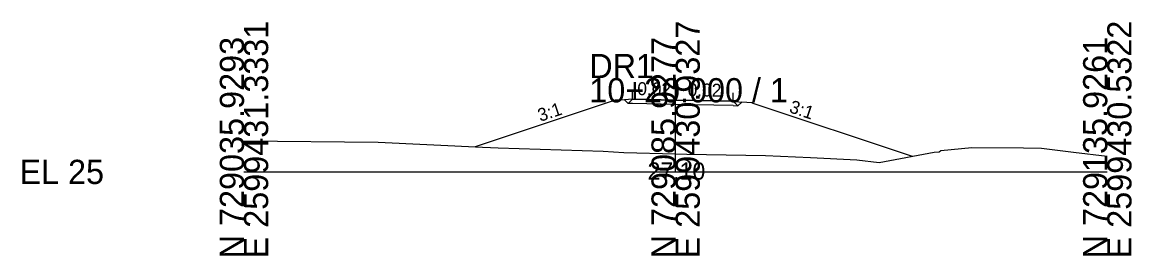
# Model space of a CAD drawing. Extents: x -26 to 1162, y -10 to 9515.
# Drawn here: x -25.7 to 102.8, y 990.3 to 1017.3 of the extents above; entities that cross this region are included whole.
import ezdxf

# ---------------------------------------------------------------- set-up
doc = ezdxf.new("R2010")
doc.units = 0
for name, color, linetype in [('Exist Cross Section Cell', 7, 'Continuous'), ('Exist XS Center Line Elevation Label', 7, 'Continuous'), ('Exist XS Ground Line', 7, 'Continuous'), ('Prop XS Ditch Slope Text', 7, 'Continuous'), ('Prop XS Dump Level', 7, 'Continuous'), ('Prop XS EOT Tick Mark', 7, 'Continuous'), ('Prop XS Finish Grade', 7, 'Continuous'), ('Prop XS Finish Grade Earthwork', 7, 'Continuous'), ('Prop XS Finish Grade Pavement', 7, 'Continuous'), ('Prop XS Pvmt Edge Slope', 7, 'Continuous'), ('Prop XS SE Text', 7, 'Continuous'), ('Prop XS Subgrade Earthwork', 7, 'Continuous')]:
    doc.layers.add(name, color=color, linetype=linetype)

msp = doc.modelspace()

# ---------------------------------------------------------------- linework, layer by layer
at = {"layer": 'Exist Cross Section Cell'}
for p, q in [((50, 1000), (50, 1010.84)), ((0, 1000), (50, 1000)), ((50, 1000), (100, 1000))]:
    msp.add_line(p, q, dxfattribs=at)
at = {"layer": 'Exist XS Ground Line'}
msp.add_lwpolyline([(0, 1003.61), (15.56, 1003.43), (27.61, 1002.87), (28.57, 1002.82), (29.44, 1002.79), (41.59, 1002.4), (44.01, 1002.25), (50, 1002.1), (51.3, 1002.07), (60.42, 1001.91), (65.62, 1001.65), (70.97, 1001.38), (73.59, 1001.09), (79.94, 1002.29), (80.51, 1002.32), (80.71, 1002.47), (84.29, 1002.84), (90.31, 1002.77), (92.36, 1002.74), (96.07, 1002.29), (100, 1001.82)], dxfattribs=at)
at = {"layer": 'Prop XS Dump Level'}
for p, q in [((50, 1008.29), (45, 1008.39)), ((50, 1008.29), (45, 1008.39)), ((56.65, 1008.16), (50, 1008.29)), ((56.65, 1008.16), (50, 1008.29))]:
    msp.add_line(p, q, dxfattribs=at)
at = {"layer": 'Prop XS EOT Tick Mark'}
for p, q in [((45, 1008.39), (45, 1009.39)), ((56.65, 1008.16), (56.65, 1009.16))]:
    msp.add_line(p, q, dxfattribs=at)
at = {"layer": 'Prop XS Finish Grade'}
for p, q in [((45, 1008.39), (44.06, 1008.35)), ((56.65, 1008.16), (57.68, 1008.08))]:
    msp.add_line(p, q, dxfattribs=at)
at = {"layer": 'Prop XS Finish Grade Earthwork'}
for p, q in [((43, 1008.31), (26.79, 1002.91)), ((44.06, 1008.35), (43, 1008.31)), ((58.83, 1008), (57.68, 1008.08)), ((58.83, 1008), (77.41, 1001.82))]:
    msp.add_line(p, q, dxfattribs=at)
at = {"layer": 'Prop XS Finish Grade Pavement'}
for p, q in [((45, 1008.39), (50, 1008.29)), ((50, 1008.29), (56.65, 1008.16))]:
    msp.add_line(p, q, dxfattribs=at)
at = {"layer": 'Prop XS Pvmt Edge Slope'}
for p, q in [((44.06, 1008.35), (44.51, 1007.9)), ((45, 1008.39), (44.51, 1007.9)), ((56.65, 1008.16), (57.21, 1007.65))]:
    msp.add_line(p, q, dxfattribs=at)
at = {"layer": 'Prop XS Subgrade Earthwork'}
for p, q in [((44.51, 1007.9), (44.06, 1008.35)), ((44.51, 1007.9), (44.06, 1008.35)), ((45, 1007.89), (44.51, 1007.9)), ((50, 1007.78), (45, 1007.89)), ((56.65, 1007.66), (50, 1007.78)), ((57.21, 1007.65), (57.68, 1008.08)), ((57.68, 1008.08), (57.21, 1007.65)), ((56.65, 1007.66), (57.21, 1007.65))]:
    msp.add_line(p, q, dxfattribs=at)

# ---------------------------------------------------------------- texts
at = {"layer": 'Exist Cross Section Cell'}
for s, p in [('E 2599431.3331', (2.8, 990)), ('E 2599430.9327', (52.8, 990)), ('E 2599430.5322', (102.8, 990)), ('N 729035.9293', (0, 990)), ('N 729085.9277', (50, 990)), ('N 729135.9261', (100, 990))]:
    msp.add_text(s, height=2.8, rotation=90, dxfattribs=at).set_placement(p)
for s, p in [('DR1', (40, 1010.84)), ('10+20.000 / 1', (40, 1008.04)), ('EL 25', (-26, 998.6))]:
    msp.add_text(s, height=2.8, dxfattribs=at).set_placement(p)
at = {"layer": 'Exist XS Center Line Elevation Label'}
msp.add_text('27.10', height=2, dxfattribs=at).set_placement((46.74, 999.1))
at = {"layer": 'Prop XS Ditch Slope Text'}
for rotation, p in [(18.4349, (34.32, 1005.78)), (341.5883, (63.06, 1006.92))]:
    msp.add_text('3:1', height=1.5, rotation=rotation, dxfattribs=at).set_placement(p)
at = {"layer": 'Prop XS Dump Level'}
for p in [(43, 1008.27), (58.83, 1007.96)]:
    msp.add_text('Case1', height=0.04, dxfattribs=at).set_placement(p)
at = {"layer": 'Prop XS SE Text'}
for p in [(45.55, 1008.88), (51.38, 1008.76)]:
    msp.add_text('0.02', height=1.5, rotation=358.8542, dxfattribs=at).set_placement(p)

doc.saveas('drawing.dxf')
